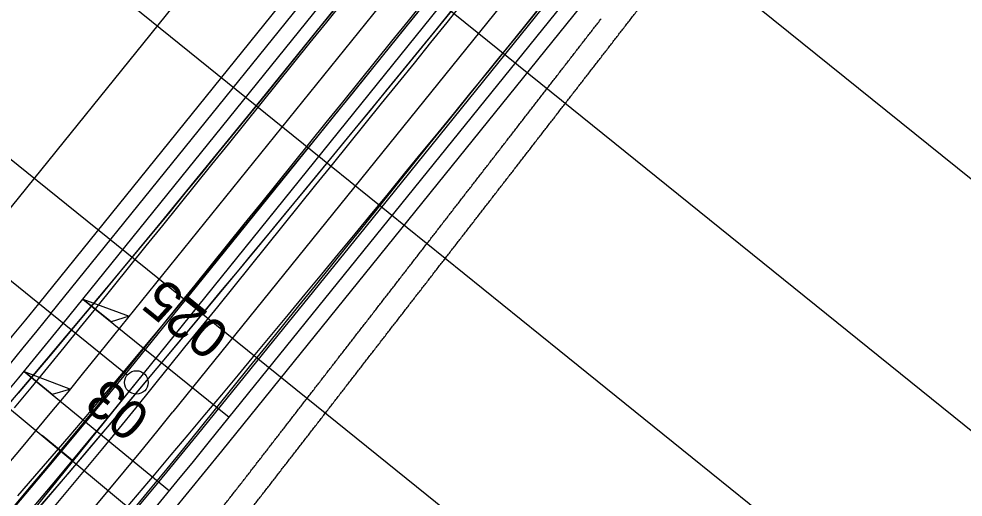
# Model space of a CAD drawing. Extents: x 2293233 to 2294507, y 892788 to 894229.
# Drawn here: x 2293748 to 2293868.5, y 893314.3 to 893375.3 of the extents above; entities that cross this region are included whole.
import ezdxf

# ---------------------------------------------------------------- set-up
doc = ezdxf.new("R2010")
doc.units = 0
for name, color, linetype in [('COGO Default Curve', 7, 'Continuous'), ('Prop EOT', 7, 'Continuous'), ('Prop Guardrail', 7, 'Continuous'), ('Prop Horizontal Alignment', 7, 'Continuous'), ('Prop Paved Shoulder', 7, 'Continuous'), ('Prop Superelevation  Arrow CELL', 7, 'Continuous'), ('Prop Superelevation Label', 7, 'Continuous'), ('Scratch_Level_4', 7, 'Continuous'), ('Scratch_Level_5', 7, 'Continuous')]:
    doc.layers.add(name, color=color, linetype=linetype)

msp = doc.modelspace()

# ---------------------------------------------------------------- linework, layer by layer
at = {"layer": 'COGO Default Curve'}
for p, q in [((2293758.37, 893332.69), (2294065.5, 893713.27)), ((2293767.71, 893325.15), (2294074.84, 893705.73))]:
    msp.add_line(p, q, dxfattribs=at)
for points in [[(2294073.94, 893697.86), (2293868.79, 893443.63), (2293792.2, 893348.66), (2293779.83, 893333.36), (2293770.79, 893322.25), (2293765.29, 893315.55), (2293760.6, 893309.91), (2293756.09, 893304.55), (2293751.76, 893299.48), (2293746.96, 893293.94), (2293742.34, 893288.69), (2293737.45, 893283.22), (2293732.75, 893278.03), (2293727.78, 893272.64), (2293722.77, 893267.28), (2293717.72, 893261.96), (2293712.86, 893256.92), (2293707.73, 893251.68), (2293702.8, 893246.71), (2293697.59, 893241.55), (2293692.58, 893236.66)], [(2294044.74, 893680.7), (2293954.06, 893568.41), (2293770.67, 893341.16), (2293761.43, 893329.77), (2293756.77, 893324.11), (2293752.51, 893318.98), (2293748.22, 893313.88), (2293744.11, 893309.05), (2293739.98, 893304.26), (2293735.81, 893299.49), (2293731.62, 893294.74), (2293727.39, 893290.03), (2293722.91, 893285.09), (2293718.62, 893280.44), (2293714.3, 893275.81), (2293709.95, 893271.21), (2293705.56, 893266.64), (2293701.15, 893262.1), (2293696.71, 893257.59), (2293692.23, 893253.11), (2293687.73, 893248.66), (2293683.19, 893244.24), (2293678.63, 893239.85)], [(2293680.14, 893237.74), (2293686.34, 893243.78), (2293692.26, 893249.64), (2293698.14, 893255.55), (2293703.96, 893261.51), (2293709.74, 893267.51), (2293715.47, 893273.56), (2293720.92, 893279.42), (2293726.55, 893285.56), (2293732.12, 893291.75), (2293737.87, 893298.24), (2293743.8, 893305.01), (2293749.89, 893312.08), (2293756.38, 893319.69), (2293763.26, 893327.84), (2293770.53, 893336.54), (2293778.4, 893346.03), (2293786.88, 893356.32), (2293796.39, 893367.93), (2293808.61, 893382.91), (2293822.69, 893400.24), (2293860.23, 893446.62), (2293932.89, 893536.61), (2294046.75, 893677.72)], [(2293687.14, 893261.63), (2293692.08, 893266.58), (2293696.99, 893271.57), (2293701.87, 893276.59), (2293706.71, 893281.65), (2293711.51, 893286.74), (2293716.29, 893291.86), (2293721.02, 893297.02), (2293725.73, 893302.2), (2293730.62, 893307.66), (2293735.48, 893313.16), (2293740.31, 893318.68), (2293745.1, 893324.23), (2293750.07, 893330.06), (2293755.02, 893335.92), (2293760.15, 893342.06), (2293765.46, 893348.48), (2293771.17, 893355.44), (2293778.96, 893365), (2293789.02, 893377.44), (2293934.91, 893558.24), (2293982.19, 893616.89)], [(2293799.79, 893377.65), (2293797.7, 893375.06), (2293795.61, 893372.46), (2293793.51, 893369.87), (2293791.42, 893367.27), (2293789.33, 893364.68), (2293787.23, 893362.09), (2293785.14, 893359.49), (2293783.04, 893356.9), (2293780.95, 893354.3), (2293778.86, 893351.71), (2293776.76, 893349.11), (2293774.67, 893346.52), (2293772.58, 893343.93), (2293770.48, 893341.33), (2293768.39, 893338.74), (2293766.3, 893336.14), (2293764.2, 893333.55), (2293762.11, 893330.95), (2293760.01, 893328.36), (2293757.9, 893325.77), (2293755.78, 893323.19), (2293753.66, 893320.61), (2293751.52, 893318.04), (2293749.37, 893315.47), (2293747.21, 893312.92)], [(2293762.72, 893312.74), (2293764.86, 893315.33), (2293766.98, 893317.91), (2293769.09, 893320.51), (2293771.2, 893323.11), (2293773.3, 893325.71), (2293775.4, 893328.31), (2293777.49, 893330.91), (2293779.59, 893333.51), (2293781.69, 893336.11), (2293783.78, 893338.71), (2293785.88, 893341.3), (2293787.98, 893343.9), (2293790.07, 893346.5), (2293792.17, 893349.09), (2293794.26, 893351.69), (2293796.36, 893354.28), (2293798.45, 893356.88), (2293800.54, 893359.47), (2293802.64, 893362.07), (2293804.73, 893364.66), (2293806.83, 893367.26), (2293808.92, 893369.85), (2293811.01, 893372.45), (2293813.11, 893375.04), (2293815.2, 893377.64)], [(2293789.38, 893377.49), (2293787.29, 893374.89), (2293785.19, 893372.3), (2293783.1, 893369.7), (2293781.01, 893367.11), (2293778.91, 893364.52), (2293776.82, 893361.92), (2293774.73, 893359.33), (2293772.63, 893356.73), (2293770.54, 893354.14), (2293768.44, 893351.54), (2293766.35, 893348.95), (2293764.26, 893346.36), (2293762.16, 893343.76), (2293760.07, 893341.17), (2293757.98, 893338.57), (2293755.88, 893335.98), (2293753.79, 893333.39), (2293751.69, 893330.81), (2293749.58, 893328.23), (2293747.46, 893325.67)], [(2293788.13, 893376.34), (2293786.04, 893373.75), (2293783.94, 893371.16), (2293781.85, 893368.57), (2293779.75, 893365.98), (2293777.65, 893363.39), (2293775.55, 893360.81), (2293773.45, 893358.23), (2293771.34, 893355.65), (2293769.24, 893353.07), (2293767.13, 893350.5), (2293765.01, 893347.93), (2293762.89, 893345.37), (2293760.77, 893342.81), (2293758.64, 893340.25), (2293756.51, 893337.7), (2293754.38, 893335.16), (2293752.23, 893332.61), (2293750.09, 893330.08), (2293747.94, 893327.55)], [(2293750.22, 893312.47), (2293752.39, 893314.99), (2293754.54, 893317.52), (2293756.69, 893320.06), (2293758.84, 893322.6), (2293760.99, 893325.14), (2293763.13, 893327.69), (2293765.27, 893330.24), (2293767.4, 893332.79), (2293769.53, 893335.35), (2293771.66, 893337.9), (2293773.79, 893340.47), (2293775.92, 893343.03), (2293778.04, 893345.59), (2293780.16, 893348.16), (2293782.28, 893350.73), (2293784.4, 893353.3), (2293786.51, 893355.87), (2293788.63, 893358.45), (2293790.74, 893361.02), (2293792.85, 893363.6), (2293794.96, 893366.18), (2293797.07, 893368.76), (2293799.18, 893371.34), (2293801.28, 893373.92), (2293803.39, 893376.5)], [(2293752.39, 893312.85), (2293754.52, 893315.4), (2293756.65, 893317.95), (2293758.76, 893320.51), (2293760.87, 893323.07), (2293762.96, 893325.65), (2293765.05, 893328.23), (2293767.14, 893330.82), (2293769.23, 893333.41), (2293771.32, 893335.99), (2293773.41, 893338.58), (2293775.5, 893341.17), (2293777.59, 893343.77), (2293779.68, 893346.36), (2293781.77, 893348.95), (2293783.86, 893351.54), (2293785.95, 893354.13), (2293788.05, 893356.73), (2293790.14, 893359.32), (2293792.23, 893361.91), (2293794.33, 893364.51), (2293796.42, 893367.1), (2293798.51, 893369.69), (2293800.61, 893372.29), (2293802.7, 893374.88), (2293804.79, 893377.48)], [(2293798.94, 893376.19), (2293796.84, 893373.6), (2293794.75, 893371), (2293792.65, 893368.41), (2293790.55, 893365.81), (2293788.45, 893363.22), (2293786.35, 893360.62), (2293784.25, 893358.03), (2293782.15, 893355.44), (2293780.04, 893352.85), (2293777.93, 893350.27), (2293775.81, 893347.68), (2293773.69, 893345.1), (2293771.57, 893342.52), (2293769.44, 893339.95), (2293767.31, 893337.38), (2293765.17, 893334.81), (2293763.03, 893332.25), (2293760.88, 893329.69), (2293758.73, 893327.13), (2293756.57, 893324.58), (2293754.4, 893322.03), (2293752.23, 893319.49), (2293750.05, 893316.96), (2293747.87, 893314.43)], [(2293761.02, 893312.02), (2293763.18, 893314.56), (2293765.34, 893317.11), (2293767.49, 893319.67), (2293769.64, 893322.22), (2293771.78, 893324.78), (2293773.92, 893327.34), (2293776.06, 893329.9), (2293778.2, 893332.47), (2293780.33, 893335.04), (2293782.46, 893337.61), (2293784.59, 893340.18), (2293786.71, 893342.75), (2293788.84, 893345.32), (2293790.96, 893347.9), (2293793.08, 893350.48), (2293795.2, 893353.05), (2293797.31, 893355.63), (2293799.43, 893358.21), (2293801.54, 893360.8), (2293803.65, 893363.38), (2293805.76, 893365.96), (2293807.87, 893368.54), (2293809.98, 893371.13), (2293812.08, 893373.71), (2293814.19, 893376.3)]]:
    msp.add_lwpolyline(points, dxfattribs=at)
msp.add_circle((2293758.37, 893332.69), 0.0417, dxfattribs=at)
msp.add_circle((2293758.37, 893332.69), 0.0417, dxfattribs=at)
for radius in [944, 956]:
    msp.add_arc((2293023.75, 893925.54), radius, 308.6085, 321.09608, dxfattribs=at)
at = {"layer": 'Prop EOT'}
for p, q in [((2293753.7, 893336.46), (2294060.83, 893717.04)), ((2293753.7, 893336.46), (2294060.83, 893717.04)), ((2293772.37, 893321.38), (2294079.51, 893701.97))]:
    msp.add_line(p, q, dxfattribs=at)
for radius, start in [(938, 309.40221), (962, 308.6085)]:
    msp.add_arc((2293023.75, 893925.54), radius, start, 321.09608, dxfattribs=at)
at = {"layer": 'Prop Guardrail'}
for points in [[(2293791.71, 893335.79), (2293792.12, 893336.32), (2293792.54, 893336.85), (2293792.95, 893337.39), (2293793.36, 893337.92), (2293793.78, 893338.46), (2293794.19, 893338.99), (2293794.6, 893339.53), (2293795.02, 893340.06), (2293795.43, 893340.59), (2293795.85, 893341.13), (2293796.26, 893341.66), (2293796.67, 893342.2), (2293797.09, 893342.73), (2293797.5, 893343.27), (2293797.91, 893343.8), (2293798.33, 893344.33), (2293798.74, 893344.87), (2293799.16, 893345.4), (2293799.57, 893345.94), (2293799.98, 893346.47), (2293800.4, 893347.01), (2293800.81, 893347.54), (2293801.23, 893348.07), (2293801.64, 893348.61), (2293802.05, 893349.14), (2293802.47, 893349.68), (2293802.88, 893350.21), (2293803.29, 893350.75), (2293803.71, 893351.28), (2293804.12, 893351.81), (2293804.54, 893352.35), (2293804.95, 893352.88), (2293805.36, 893353.42), (2293805.78, 893353.95), (2293806.19, 893354.49), (2293806.61, 893355.02), (2293807.02, 893355.55), (2293807.43, 893356.09), (2293807.85, 893356.62), (2293808.26, 893357.16), (2293808.67, 893357.69), (2293809.09, 893358.23), (2293809.5, 893358.76), (2293809.92, 893359.29), (2293810.33, 893359.83), (2293810.74, 893360.36), (2293811.16, 893360.9), (2293811.57, 893361.43), (2293811.98, 893361.97), (2293812.4, 893362.5), (2293812.81, 893363.04), (2293813.23, 893363.57), (2293813.64, 893364.1), (2293814.05, 893364.64), (2293814.47, 893365.17), (2293814.88, 893365.71), (2293815.3, 893366.24), (2293815.71, 893366.78), (2293816.12, 893367.31), (2293816.54, 893367.84), (2293816.95, 893368.38), (2293817.36, 893368.91), (2293817.78, 893369.45), (2293818.19, 893369.98), (2293818.61, 893370.52), (2293819.02, 893371.05), (2293819.43, 893371.58), (2293819.85, 893372.12), (2293820.26, 893372.65), (2293820.67, 893373.19), (2293821.09, 893373.72), (2293821.5, 893374.26), (2293821.92, 893374.79), (2293822.33, 893375.32)], [(2293760.46, 893296.08), (2293760.89, 893296.61), (2293761.33, 893297.14), (2293761.77, 893297.67), (2293762.2, 893298.21), (2293762.64, 893298.74), (2293763.07, 893299.28), (2293763.51, 893299.81), (2293763.94, 893300.35), (2293764.38, 893300.88), (2293764.81, 893301.42), (2293765.24, 893301.95), (2293765.68, 893302.49), (2293766.11, 893303.03), (2293766.54, 893303.56), (2293766.97, 893304.1), (2293767.41, 893304.64), (2293767.84, 893305.18), (2293768.27, 893305.71), (2293768.7, 893306.25), (2293769.13, 893306.79), (2293769.56, 893307.33), (2293769.99, 893307.87), (2293770.41, 893308.41), (2293770.84, 893308.95), (2293771.27, 893309.49), (2293771.7, 893310.03), (2293772.13, 893310.57), (2293772.55, 893311.11), (2293772.98, 893311.65), (2293773.4, 893312.19), (2293773.83, 893312.74), (2293774.25, 893313.28), (2293774.68, 893313.82), (2293775.1, 893314.36), (2293775.53, 893314.91), (2293775.95, 893315.45), (2293776.37, 893315.99), (2293776.8, 893316.54), (2293777.22, 893317.08), (2293777.64, 893317.62), (2293778.05, 893318.15), (2293778.47, 893318.69), (2293778.88, 893319.22), (2293779.29, 893319.76), (2293779.71, 893320.29), (2293780.12, 893320.83), (2293780.53, 893321.36), (2293780.95, 893321.89), (2293781.36, 893322.43), (2293781.78, 893322.96), (2293782.19, 893323.5), (2293782.6, 893324.03), (2293783.02, 893324.57), (2293783.43, 893325.1), (2293783.84, 893325.63), (2293784.26, 893326.17), (2293784.67, 893326.7), (2293785.09, 893327.24), (2293785.5, 893327.77), (2293785.91, 893328.31), (2293786.33, 893328.84), (2293786.74, 893329.37), (2293787.16, 893329.91), (2293787.57, 893330.44), (2293787.98, 893330.98), (2293788.4, 893331.51), (2293788.81, 893332.05), (2293789.22, 893332.58), (2293789.64, 893333.11), (2293790.05, 893333.65), (2293790.47, 893334.18), (2293790.88, 893334.72), (2293791.29, 893335.25), (2293791.71, 893335.79)]]:
    msp.add_spline(points, degree=3, dxfattribs=at)
at = {"layer": 'Prop Horizontal Alignment'}
for p, q in [((2293763.04, 893328.92), (2294070.17, 893709.5)), ((2293763.04, 893328.92), (2294070.17, 893709.5)), ((2293761.87, 893329.86), (2293549.03, 893501.62)), ((2293754.87, 893318.94), (2293751.02, 893322.13))]:
    msp.add_line(p, q, dxfattribs=at)
msp.add_circle((2293763.04, 893328.92), 1.5, dxfattribs=at)
msp.add_arc((2293023.75, 893925.54), 950, 308.6085, 321.09608, dxfattribs=at)
msp.add_arc((2293023.75, 893925.54), 950, 308.6085, 321.09608, dxfattribs=at)
at = {"layer": 'Prop Paved Shoulder'}
for p, q in [((2293752.14, 893337.71), (2294059.27, 893718.29)), ((2293773.93, 893320.13), (2294081.06, 893700.71))]:
    msp.add_line(p, q, dxfattribs=at)
for radius, start in [(936, 310.01837), (964, 308.6085)]:
    msp.add_arc((2293023.75, 893925.54), radius, start, 321.09608, dxfattribs=at)
at = {"layer": 'Prop Superelevation  Arrow CELL'}
for p, q in [((2293756.21, 893339.57), (2293774.89, 893324.5)), ((2293748.71, 893330.33), (2293767.26, 893315.1))]:
    msp.add_line(p, q, dxfattribs=at)
for points in [[(2293756.21, 893339.57), (2293762.13, 893337.36), (2293759.81, 893336.66)], [(2293748.71, 893330.33), (2293754.62, 893328.07), (2293752.29, 893327.39)]]:
    msp.add_lwpolyline(points, close=True, dxfattribs=at)
at = {"layer": 'Scratch_Level_4'}
for p, q in [((2293708.32, 893261.12), (2294130.82, 893784.65)), ((2293701.01, 893490.9), (2293934.47, 893302.5)), ((2293685.31, 893471.45), (2293918.77, 893283.04)), ((2293669.61, 893451.99), (2293903.07, 893263.59)), ((2293653.9, 893432.54), (2293887.36, 893244.13)), ((2293639.43, 893414.71), (2293870.31, 893223.16))]:
    msp.add_line(p, q, dxfattribs=at)
at = {"layer": 'Scratch_Level_5'}
for p, q in [((2293750.59, 893338.97), (2293936.67, 893569.56)), ((2293676.84, 893264.33), (2293818.17, 893439.42))]:
    msp.add_line(p, q, dxfattribs=at)
msp.add_arc((2293023.75, 893925.54), 934, 310.67386, 321.09608, dxfattribs=at)
for points in [[(2293824.7, 893373.49), (2293825.12, 893374.02), (2293825.53, 893374.56), (2293825.94, 893375.09), (2293826.36, 893375.62), (2293826.77, 893376.16), (2293827.18, 893376.69), (2293827.6, 893377.23), (2293828.01, 893377.76), (2293828.43, 893378.3), (2293828.84, 893378.83), (2293829.25, 893379.36), (2293829.67, 893379.9), (2293830.08, 893380.43), (2293830.5, 893380.97), (2293830.91, 893381.5), (2293831.32, 893382.04), (2293831.74, 893382.57), (2293832.15, 893383.1), (2293832.56, 893383.64), (2293832.98, 893384.17), (2293833.39, 893384.71), (2293833.81, 893385.24), (2293834.22, 893385.78), (2293834.63, 893386.31), (2293835.05, 893386.84), (2293835.46, 893387.38), (2293835.88, 893387.91), (2293836.29, 893388.45), (2293836.7, 893388.98), (2293837.12, 893389.52), (2293837.53, 893390.05), (2293837.94, 893390.58), (2293838.36, 893391.12), (2293838.77, 893391.65), (2293839.19, 893392.19), (2293839.6, 893392.72), (2293840.01, 893393.26), (2293840.43, 893393.79), (2293840.84, 893394.32), (2293841.25, 893394.86), (2293841.67, 893395.39), (2293842.08, 893395.93), (2293842.5, 893396.46), (2293842.91, 893397), (2293843.32, 893397.53), (2293843.74, 893398.06), (2293844.15, 893398.6), (2293844.57, 893399.13), (2293844.98, 893399.67), (2293845.39, 893400.2), (2293845.81, 893400.74), (2293846.22, 893401.27), (2293846.63, 893401.8), (2293847.05, 893402.34), (2293847.46, 893402.87), (2293847.88, 893403.41), (2293848.29, 893403.94), (2293848.7, 893404.48), (2293849.12, 893405.01), (2293849.53, 893405.54), (2293849.94, 893406.08), (2293850.36, 893406.61), (2293850.77, 893407.15), (2293851.19, 893407.68), (2293851.6, 893408.22), (2293852.01, 893408.75), (2293852.43, 893409.28), (2293852.84, 893409.82), (2293853.26, 893410.35), (2293853.67, 893410.89), (2293854.08, 893411.42), (2293854.5, 893411.96), (2293855.32, 893413.02)], [(2293794.08, 893333.95), (2293794.49, 893334.48), (2293794.91, 893335.02), (2293795.32, 893335.55), (2293795.73, 893336.09), (2293796.15, 893336.62), (2293796.56, 893337.15), (2293796.98, 893337.69), (2293797.39, 893338.22), (2293797.8, 893338.76), (2293798.22, 893339.29), (2293798.63, 893339.83), (2293799.05, 893340.36), (2293799.46, 893340.89), (2293799.87, 893341.43), (2293800.29, 893341.96), (2293800.7, 893342.5), (2293801.11, 893343.03), (2293801.53, 893343.57), (2293801.94, 893344.1), (2293802.36, 893344.63), (2293802.77, 893345.17), (2293803.18, 893345.7), (2293803.6, 893346.24), (2293804.01, 893346.77), (2293804.42, 893347.31), (2293804.84, 893347.84), (2293805.25, 893348.37), (2293805.67, 893348.91), (2293806.08, 893349.44), (2293806.49, 893349.98), (2293806.91, 893350.51), (2293807.32, 893351.05), (2293807.74, 893351.58), (2293808.15, 893352.11), (2293808.56, 893352.65), (2293808.98, 893353.18), (2293809.39, 893353.72), (2293809.8, 893354.25), (2293810.22, 893354.79), (2293810.63, 893355.32), (2293811.05, 893355.86), (2293811.46, 893356.39), (2293811.87, 893356.92), (2293812.29, 893357.46), (2293812.7, 893357.99), (2293813.12, 893358.53), (2293813.53, 893359.06), (2293813.94, 893359.6), (2293814.36, 893360.13), (2293814.77, 893360.66), (2293815.18, 893361.2), (2293815.6, 893361.73), (2293816.01, 893362.27), (2293816.43, 893362.8), (2293816.84, 893363.34), (2293817.25, 893363.87), (2293817.67, 893364.4), (2293818.08, 893364.94), (2293818.49, 893365.47), (2293818.91, 893366.01), (2293819.32, 893366.54), (2293819.74, 893367.08), (2293820.15, 893367.61), (2293820.56, 893368.14), (2293820.98, 893368.68), (2293821.39, 893369.21), (2293821.81, 893369.75), (2293822.22, 893370.28), (2293822.63, 893370.82), (2293823.05, 893371.35), (2293823.46, 893371.88), (2293823.87, 893372.42), (2293824.29, 893372.95), (2293824.7, 893373.49)], [(2293762.77, 893294.17), (2293763.21, 893294.71), (2293763.65, 893295.24), (2293764.09, 893295.78), (2293764.53, 893296.31), (2293764.96, 893296.85), (2293765.4, 893297.38), (2293765.84, 893297.92), (2293766.27, 893298.46), (2293766.71, 893298.99), (2293767.14, 893299.53), (2293767.58, 893300.07), (2293768.01, 893300.61), (2293768.45, 893301.14), (2293768.88, 893301.68), (2293769.31, 893302.22), (2293769.75, 893302.76), (2293770.18, 893303.3), (2293770.61, 893303.84), (2293771.04, 893304.38), (2293771.47, 893304.92), (2293771.9, 893305.46), (2293772.33, 893306), (2293772.76, 893306.54), (2293773.19, 893307.08), (2293773.62, 893307.63), (2293774.05, 893308.17), (2293774.48, 893308.71), (2293774.91, 893309.25), (2293775.34, 893309.8), (2293775.76, 893310.34), (2293776.19, 893310.88), (2293776.62, 893311.43), (2293777.04, 893311.97), (2293777.47, 893312.52), (2293777.89, 893313.06), (2293778.32, 893313.61), (2293778.74, 893314.15), (2293779.17, 893314.7), (2293779.59, 893315.24), (2293780.01, 893315.78), (2293780.42, 893316.32), (2293780.84, 893316.85), (2293781.25, 893317.39), (2293781.66, 893317.92), (2293782.08, 893318.45), (2293782.49, 893318.99), (2293782.91, 893319.52), (2293783.32, 893320.06), (2293783.73, 893320.59), (2293784.15, 893321.13), (2293784.56, 893321.66), (2293784.98, 893322.19), (2293785.39, 893322.73), (2293785.8, 893323.26), (2293786.22, 893323.8), (2293786.63, 893324.33), (2293787.04, 893324.87), (2293787.46, 893325.4), (2293787.87, 893325.93), (2293788.29, 893326.47), (2293788.7, 893327), (2293789.11, 893327.54), (2293789.53, 893328.07), (2293789.94, 893328.61), (2293790.35, 893329.14), (2293790.77, 893329.67), (2293791.18, 893330.21), (2293791.6, 893330.74), (2293792.01, 893331.28), (2293792.42, 893331.81), (2293792.84, 893332.35), (2293793.25, 893332.88), (2293793.67, 893333.41), (2293794.08, 893333.95)]]:
    msp.add_spline(points, degree=3, dxfattribs=at)

# ---------------------------------------------------------------- texts
at = {"layer": 'Prop Superelevation Label'}
for s, rotation, p in [('025', 141.0961, (2293775.22, 893335.43)), ('03', 140.6135, (2293765.07, 893324.97))]:
    msp.add_text(s, height=5, rotation=rotation, dxfattribs=at).set_placement(p)

doc.saveas('drawing.dxf')
